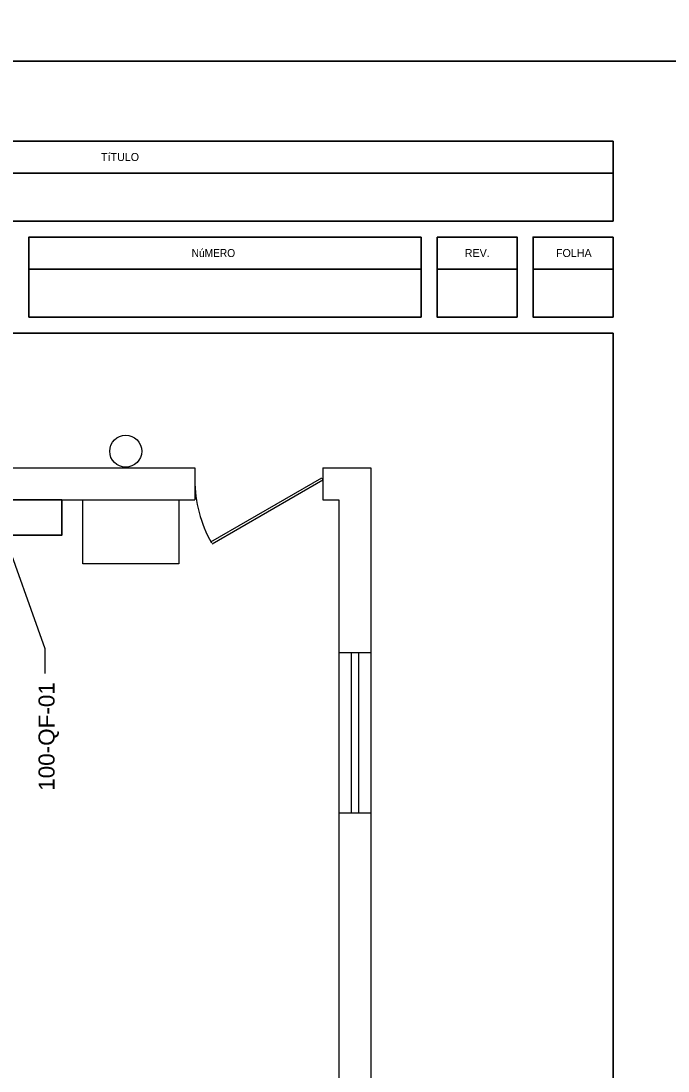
# Model space of a CAD drawing. Extents: x -4160 to -2690, y -474 to 714.
# Drawn here: x -3404.8 to -3323.9, y 291.3 to 422.5 of the extents above; entities that cross this region are included whole.
import ezdxf
from ezdxf.enums import TextEntityAlignment as Align

# ---------------------------------------------------------------- set-up
doc = ezdxf.new("R2010")
doc.units = 0
doc.header["$LTSCALE"] = 0.56
for name, color, linetype, lineweight in [('1', 7, 'Continuous', 25), ('2', 7, 'Continuous', 25), ('5', 7, 'Continuous', 35)]:
    doc.layers.add(name, color=color, linetype=linetype, lineweight=lineweight)

msp = doc.modelspace()

# ---------------------------------------------------------------- linework, layer by layer
at = {"layer": '1'}
for p, q in [((-3481.0303, 366.6544), (-3383.0303, 366.6544)), ((-3383.0303, 366.6544), (-3383.0303, 362.6544)), ((-3367.0303, 366.6544), (-3367.0303, 362.6544)), ((-3367.0303, 366.6544), (-3361.0303, 366.6544)), ((-3361.0303, 366.6544), (-3361.0303, 343.5704)), ((-3380.8863, 357.1544), (-3367.0303, 365.1544)), ((-3477.0303, 362.6544), (-3383.0303, 362.6544)), ((-3411.0303, 362.6544), (-3394.7063, 362.6544)), ((-3367.0303, 362.6544), (-3365.0303, 362.6544)), ((-3365.0303, 362.6544), (-3365.0303, 343.5704)), ((-3365.0303, 343.5704), (-3365.0303, 323.5704)), ((-3365.0303, 343.5704), (-3361.0303, 343.5704)), ((-3365.0303, 342.4504), (-3365.0303, 324.4904)), ((-3363.4943, 343.5704), (-3363.4943, 323.5704)), ((-3362.6023, 343.5704), (-3362.6023, 323.5704)), ((-3361.0303, 343.5704), (-3361.0303, 323.5704)), ((-3365.0303, 335.0704), (-3365.0303, 332.0704)), ((-3365.0303, 323.5704), (-3361.0303, 323.5704)), ((-3365.0303, 323.5704), (-3365.0303, 285.6544)), ((-3361.0303, 323.5704), (-3361.0303, 285.6544))]:
    msp.add_line(p, q, dxfattribs=at)
for points in [[(-3381.0423, 357.4264), (-3367.1863, 365.4264), (-3367.0303, 365.1544)], [(-3401.7594, 340.961), (-3401.7594, 344.0266), (-3407.2049, 359.3547)]]:
    msp.add_lwpolyline(points, dxfattribs=at)
msp.add_lwpolyline([(-3397.0303, 354.6544), (-3397.0303, 362.6544), (-3385.0303, 362.6544), (-3385.0303, 354.6544)], close=True, dxfattribs=at)
msp.add_arc((-3367.0313, 365.1534), 16, 180, 209.43929, dxfattribs=at)
at = {"layer": '2'}
msp.add_circle((-3391.6793, 368.7294), 2, dxfattribs=at)
at = {"layer": '5'}
for p, q in [((-3447.7642, 403.48), (-3330.7642, 403.48)), ((-3403.7642, 391.48), (-3354.7642, 391.48)), ((-3352.7642, 391.48), (-3342.7642, 391.48)), ((-3340.7642, 391.48), (-3330.7642, 391.48))]:
    msp.add_line(p, q, dxfattribs=at)
at = {"layer": '5', "lineweight": 25}
msp.add_lwpolyline([(-3319.7642, 417.48), (-3529.7642, 417.48), (-3529.7642, 714.48), (-3319.7642, 714.48)], close=True, dxfattribs=at)
msp.add_lwpolyline([(-3529.7642, 417.48), (-3319.7642, 417.48), (-3319.7642, 120.48)], dxfattribs=at)
at = {"layer": '5'}
for points in [[(-3330.7642, 407.48), (-3447.7642, 407.48), (-3447.7642, 397.48), (-3330.7642, 397.48)], [(-3354.7642, 395.48), (-3403.7642, 395.48), (-3403.7642, 385.48), (-3354.7642, 385.48)], [(-3352.7642, 395.48), (-3342.7642, 395.48), (-3342.7642, 385.48), (-3352.7642, 385.48)], [(-3330.7642, 395.48), (-3340.7642, 395.48), (-3340.7642, 385.48), (-3330.7642, 385.48)], [(-3504.7642, 130.48), (-3504.7642, 383.48), (-3330.7642, 383.48), (-3330.7642, 130.48)], [(-3412.6583, 358.2464), (-3412.6583, 362.6464), (-3399.6583, 362.6464), (-3399.6583, 358.2464)]]:
    msp.add_lwpolyline(points, close=True, dxfattribs=at)

# ---------------------------------------------------------------- texts
at = {"layer": '2', "width": 1.05}
msp.add_text('100-QF-01', height=2, rotation=90, dxfattribs=at).set_placement((-3400.5714, 333.0922), align=Align.CENTER)
at = {"layer": '5'}
for s, p in [('TíTULO', (-3392.3847, 404.991)), ('REV.', (-3347.7443, 392.9923)), ('FOLHA', (-3335.6809, 392.9923))]:
    msp.add_text(s, height=1, dxfattribs=at).set_placement(p, align=Align.CENTER)
at = {"layer": '5', "width": 0.95}
msp.add_text('NúMERO', height=1, dxfattribs=at).set_placement((-3380.7228, 392.9923), align=Align.CENTER)

doc.saveas('drawing.dxf')
